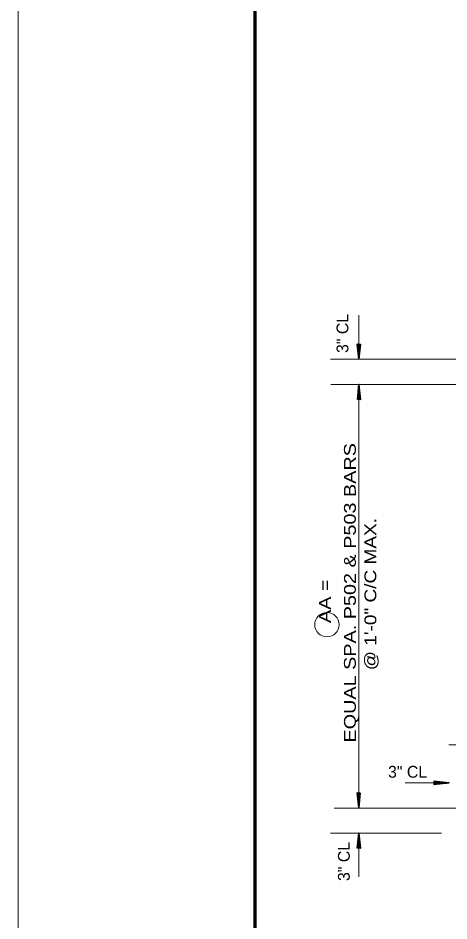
# Model space of a CAD drawing. Extents: x 4.49 to 7.69, y 0.28 to 2.27.
# Drawn here: x 4.492 to 4.796, y 0.621 to 1.256 of the extents above; entities that cross this region are included whole.
import ezdxf
from ezdxf.enums import TextEntityAlignment as Align

# ---------------------------------------------------------------- set-up
doc = ezdxf.new("R2010")
doc.units = 0
doc.header["$LTSCALE"] = 0.0033
doc.layers.add('1', color=7, linetype='Continuous', lineweight=35)

msp = doc.modelspace()

# ---------------------------------------------------------------- linework, layer by layer
at = {"layer": '1', "lineweight": 13}
for p, q in [((4.492417, 0.281583), (4.492417, 2.269833)), ((4.732333, 1.025833), (4.732333, 1.046667)), ((4.8765, 1.01575), (4.712417, 1.01575)), ((4.88975, 0.998083), (4.7125, 0.998083)), ((4.73225, 0.7005), (4.73225, 0.99725)), ((4.795667, 0.7445), (4.878583, 0.7445)), ((4.764917, 0.717833), (4.78575, 0.717833)), ((4.8905, 0.700083), (4.714917, 0.700083)), ((4.7905, 0.682417), (4.712417, 0.682417)), ((4.73225, 0.651667), (4.73225, 0.6725))]:
    msp.add_line(p, q, dxfattribs=at)
at = {"layer": '1'}
for p, q in [((4.73125, 1.026167), (4.732083, 1.018833)), ((4.731417, 1.026167), (4.732167, 1.018833)), ((4.7315, 1.026167), (4.732333, 1.018833)), ((4.731667, 1.02625), (4.732417, 1.018917)), ((4.733167, 1.026167), (4.732167, 1.018333)), ((4.732333, 1.026417), (4.732333, 1.015833)), ((4.733167, 1.026167), (4.732333, 1.018333)), ((4.733333, 1.026167), (4.732417, 1.018333)), ((4.733333, 1.026167), (4.732417, 1.018333)), ((4.73325, 1.026167), (4.732417, 1.018333)), ((4.732333, 0.9875), (4.732333, 0.998083)), ((4.731333, 0.98775), (4.73225, 0.995583)), ((4.731333, 0.98775), (4.73225, 0.995583)), ((4.731417, 0.98775), (4.73225, 0.995583)), ((4.7315, 0.98775), (4.732333, 0.995583)), ((4.7315, 0.98775), (4.7325, 0.995583)), ((4.733, 0.987667), (4.73225, 0.995)), ((4.733167, 0.98775), (4.732333, 0.995083)), ((4.73325, 0.98775), (4.7325, 0.995083)), ((4.733417, 0.98775), (4.732583, 0.995083)), ((4.785083, 0.717833), (4.795667, 0.717833)), ((4.78525, 0.717167), (4.792583, 0.717917)), ((4.785333, 0.718833), (4.793167, 0.717917)), ((4.785333, 0.718833), (4.793167, 0.717917)), ((4.785333, 0.71875), (4.793167, 0.717917)), ((4.785333, 0.718667), (4.793167, 0.717833)), ((4.785333, 0.718667), (4.793167, 0.717667)), ((4.785333, 0.717), (4.792667, 0.717833)), ((4.785333, 0.716917), (4.792667, 0.717667)), ((4.785333, 0.71675), (4.792667, 0.717583)), ((4.731167, 0.7105), (4.732, 0.703167)), ((4.731333, 0.7105), (4.732083, 0.703167)), ((4.731417, 0.7105), (4.73225, 0.703167)), ((4.731583, 0.710583), (4.732333, 0.70325)), ((4.733083, 0.7105), (4.732083, 0.702667)), ((4.73225, 0.71075), (4.73225, 0.700167)), ((4.733083, 0.7105), (4.73225, 0.702667)), ((4.73325, 0.7105), (4.732333, 0.702667)), ((4.73325, 0.7105), (4.732333, 0.702667)), ((4.733167, 0.7105), (4.732333, 0.702667)), ((4.73125, 0.672083), (4.732167, 0.679917)), ((4.73125, 0.672083), (4.732167, 0.679917)), ((4.731333, 0.672083), (4.732167, 0.679917)), ((4.731417, 0.672083), (4.73225, 0.679917)), ((4.731417, 0.672083), (4.732417, 0.679917)), ((4.73225, 0.671833), (4.73225, 0.682417)), ((4.732917, 0.672), (4.732167, 0.679333)), ((4.733083, 0.672083), (4.73225, 0.679417)), ((4.733167, 0.672083), (4.732417, 0.679417)), ((4.733333, 0.672083), (4.7325, 0.679417))]:
    msp.add_line(p, q, dxfattribs=at)
at = {"layer": '1', "lineweight": 70}
msp.add_lwpolyline([(7.605833, 0.366083), (7.605833, 2.186167), (4.659167, 2.186167), (4.659167, 0.366083)], dxfattribs=at)
at = {"layer": '1'}
for points in [[(4.733417, 1.026417), (4.732333, 1.015833), (4.731167, 1.026417), (4.732333, 1.025833)], [(4.732417, 1.025667), (4.7325, 1.021), (4.732417, 1.021), (4.732417, 1.021917), (4.7325, 1.025667), (4.732583, 1.022667), (4.732667, 1.025833), (4.73275, 1.023583), (4.732833, 1.025833), (4.732583, 1.022333), (4.732417, 1.017667), (4.732167, 1.018583), (4.732167, 1.017333), (4.732167, 1.025667), (4.732, 1.02325), (4.732, 1.025833), (4.732417, 1.0205), (4.73175, 1.025833)], [(4.73125, 0.9875), (4.732333, 0.998083), (4.7335, 0.9875), (4.732333, 0.988083)], [(4.73225, 0.98825), (4.732167, 0.992917), (4.73225, 0.992917), (4.73225, 0.992), (4.732167, 0.98825), (4.732083, 0.99125), (4.732, 0.988083), (4.731917, 0.990333), (4.731833, 0.988083), (4.732083, 0.991583), (4.73225, 0.99625), (4.7325, 0.995333), (4.7325, 0.996583), (4.7325, 0.98825), (4.732667, 0.990667), (4.732667, 0.988083), (4.73225, 0.993417), (4.732917, 0.988083)], [(4.785083, 0.718917), (4.795667, 0.717833), (4.785083, 0.716667), (4.785667, 0.717833)], [(4.785833, 0.717917), (4.7905, 0.718), (4.7905, 0.717917), (4.789583, 0.717917), (4.785833, 0.718), (4.788833, 0.718083), (4.785667, 0.718167), (4.787917, 0.71825), (4.785667, 0.718333), (4.789167, 0.718083), (4.793833, 0.717917), (4.792917, 0.717667), (4.794167, 0.717667), (4.785833, 0.717667), (4.78825, 0.7175), (4.785667, 0.7175), (4.791, 0.717917), (4.785667, 0.71725)], [(4.733333, 0.71075), (4.73225, 0.700167), (4.731083, 0.71075), (4.73225, 0.710167)], [(4.732333, 0.71), (4.732417, 0.705333), (4.732333, 0.705333), (4.732333, 0.70625), (4.732417, 0.71), (4.7325, 0.707), (4.732583, 0.710167), (4.732667, 0.707917), (4.73275, 0.710167), (4.7325, 0.706667), (4.732333, 0.702), (4.732083, 0.702917), (4.732083, 0.701667), (4.732083, 0.71), (4.731917, 0.707583), (4.731917, 0.710167), (4.732333, 0.704833), (4.731667, 0.710167)], [(4.731167, 0.671833), (4.73225, 0.682417), (4.733417, 0.671833), (4.73225, 0.672417)], [(4.732167, 0.672583), (4.732083, 0.67725), (4.732167, 0.67725), (4.732167, 0.676333), (4.732083, 0.672583), (4.732, 0.675583), (4.731917, 0.672417), (4.731833, 0.674667), (4.73175, 0.672417), (4.732, 0.675917), (4.732167, 0.680583), (4.732417, 0.679667), (4.732417, 0.680917), (4.732417, 0.672583), (4.732583, 0.675), (4.732583, 0.672417), (4.732167, 0.67775), (4.732833, 0.672417)]]:
    msp.add_lwpolyline(points, close=True, dxfattribs=at)
for points in [[(4.732417, 1.025667), (4.733167, 1.026083), (4.732917, 1.025833), (4.732583, 1.025667), (4.732667, 1.025417), (4.733, 1.025583), (4.73225, 1.02575), (4.73175, 1.025917), (4.731333, 1.026167)], [(4.73225, 0.98825), (4.7315, 0.987833), (4.73175, 0.988083), (4.732083, 0.98825), (4.732, 0.9885), (4.731667, 0.988333), (4.732417, 0.988167), (4.732917, 0.988), (4.733333, 0.98775)], [(4.785833, 0.717917), (4.785417, 0.718667), (4.785667, 0.718417), (4.785833, 0.718083), (4.786083, 0.718167), (4.785917, 0.7185), (4.78575, 0.71775), (4.785583, 0.71725), (4.785333, 0.716833)], [(4.732333, 0.71), (4.733083, 0.710417), (4.732833, 0.710167), (4.7325, 0.71), (4.732583, 0.70975), (4.732917, 0.709917), (4.732167, 0.710083), (4.731667, 0.71025), (4.73125, 0.7105)], [(4.732167, 0.672583), (4.731417, 0.672167), (4.731667, 0.672417), (4.732, 0.672583), (4.731917, 0.672833), (4.731583, 0.672667), (4.732333, 0.6725), (4.732833, 0.672333), (4.73325, 0.672083)]]:
    msp.add_lwpolyline(points, dxfattribs=at)
at = {"layer": '1', "lineweight": 13}
msp.add_circle((4.709833, 0.829083), 0.008584, dxfattribs=at)

# ---------------------------------------------------------------- texts
at = {"layer": '1'}
for p in [(4.724917, 1.020167), (4.725917, 0.64875)]:
    msp.add_text('3" CL', height=0.008334, rotation=90, dxfattribs=at).set_placement(p)
for s, width, p in [('EQUAL SPA. P502 & P503 BARS', 1.25, (4.730167, 0.746167)), ('@ 1\'-0" C/C MAX.', 1.2, (4.744583, 0.797))]:
    msp.add_text(s, height=0.008334, rotation=90, dxfattribs=dict(at, width=width)).set_placement(p)
at = {"layer": '1', "width": 1.25}
msp.add_text('AA =      ', height=0.008334, rotation=90, dxfattribs=at).set_placement((4.712583, 0.857125), align=Align.CENTER)
at = {"layer": '1'}
msp.add_text('3" CL', height=0.008334, dxfattribs=at).set_placement((4.752833, 0.721417))

doc.saveas('drawing.dxf')
